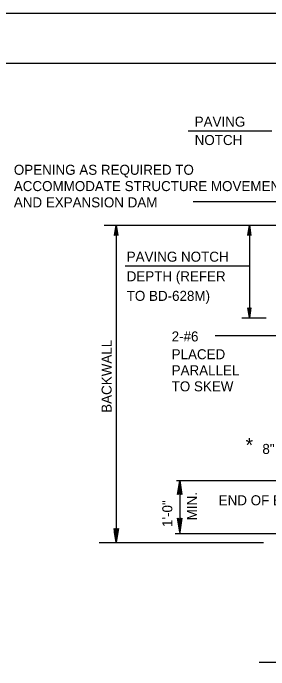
# Model space of a CAD drawing. Extents: x 638653 to 642302, y 298557 to 300414.
# Drawn here: x 640382.5 to 640459.2, y 300142.1 to 300338.5 of the extents above; entities that cross this region are included whole.
import ezdxf

# ---------------------------------------------------------------- set-up
doc = ezdxf.new("R2010")
doc.units = 0
doc.layers.add('1', color=7, linetype='Continuous')
doc.layers.add('PLT-BNDY', color=7, linetype='Continuous')

msp = doc.modelspace()

# ---------------------------------------------------------------- linework, layer by layer
at = {"layer": '1'}
for p, q in [((639863.16, 300323.52), (640649.16, 300323.52)), ((640459.99, 300303.19), (640434.96, 300303.19)), ((640436.48, 300282.18), (640481.83, 300282.18)), ((640409.78, 300275.05), (640472.49, 300275.05)), ((640413.42, 300275.05), (640413.42, 300180.15)), ((640453.3, 300275.05), (640453.3, 300247.34)), ((640416.12, 300262.89), (640453.3, 300262.89)), ((640451.07, 300247.34), (640458.32, 300247.34)), ((640443.08, 300242.12), (640499.13, 300242.12)), ((640431.48, 300198.74), (640503.46, 300198.74)), ((640432.43, 300198.69), (640432.43, 300182.8)), ((640432.43, 300198.38), (640432.43, 300183.22)), ((640431.1, 300182.8), (640496.8, 300182.8)), ((640408.27, 300180.15), (640457.51, 300180.15)), ((640456.22, 300144.37), (640490.46, 300144.37))]:
    msp.add_line(p, q, dxfattribs=at)
for points in [[(640413.06, 300272.14), (640413.27, 300272.25), (640413.42, 300275.05), (640413.06, 300272.14), (640412.93, 300271.99), (640413.42, 300275.05), (640413.56, 300272.25), (640413.77, 300272.15), (640413.42, 300275.05), (640413.91, 300271.99), (640413.77, 300272.15)], [(640452.93, 300272.14), (640453.14, 300272.25), (640453.3, 300275.05), (640452.93, 300272.14), (640452.81, 300271.99), (640453.3, 300275.05), (640453.44, 300272.25), (640453.65, 300272.15), (640453.3, 300275.05), (640453.78, 300271.99), (640453.65, 300272.15)], [(640453.66, 300250.24), (640453.45, 300250.13), (640453.3, 300247.34), (640453.66, 300250.24), (640453.79, 300250.39), (640453.3, 300247.34), (640453.16, 300250.13), (640452.95, 300250.23), (640453.3, 300247.34), (640452.81, 300250.39), (640452.95, 300250.23)], [(640431.96, 300194.63), (640432.27, 300194.79), (640432.43, 300198.69), (640431.96, 300194.63), (640431.81, 300194.47), (640432.43, 300198.69), (640432.59, 300194.79), (640432.9, 300194.63), (640432.43, 300198.69), (640433.06, 300194.47), (640432.9, 300194.63)], [(640431.96, 300194.63), (640432.27, 300194.79), (640432.43, 300198.69), (640431.96, 300194.63), (640431.81, 300194.47), (640432.43, 300198.69), (640432.59, 300194.79), (640432.9, 300194.63), (640432.43, 300198.69), (640433.06, 300194.47), (640432.9, 300194.63)], [(640432.9, 300187.29), (640432.59, 300187.13), (640432.43, 300183.22), (640432.9, 300187.29), (640433.06, 300187.44), (640432.43, 300183.22), (640432.27, 300187.13), (640431.96, 300187.29), (640432.43, 300183.22), (640431.81, 300187.44), (640431.96, 300187.29)], [(640413.89, 300184.21), (640413.58, 300184.05), (640413.42, 300180.15), (640413.89, 300184.21), (640414.05, 300184.37), (640413.42, 300180.15), (640413.27, 300184.05), (640412.96, 300184.21), (640413.42, 300180.15), (640412.8, 300184.37), (640412.96, 300184.21)], [(640413.79, 300183.05), (640413.58, 300182.95), (640413.42, 300180.15), (640413.79, 300183.05), (640413.92, 300183.2), (640413.42, 300180.15), (640413.29, 300182.94), (640413.08, 300183.05), (640413.42, 300180.15), (640412.94, 300183.2), (640413.08, 300183.05)]]:
    msp.add_lwpolyline(points, dxfattribs=at)
at = {"layer": 'PLT-BNDY'}
msp.add_lwpolyline([(639823.16, 300338.52), (640664.16, 300338.52), (640664.16, 299744.52), (639823.16, 299744.52)], close=True, dxfattribs=at)

# ---------------------------------------------------------------- texts
at = {"layer": '1'}
for s, height, p in [('PAVING', 3, (640436.92, 300304.55)), ('NOTCH', 3, (640436.92, 300299.06)), ('OPENING AS REQUIRED TO', 3, (640382.73, 300290.16)), ('ACCOMMODATE STRUCTURE MOVEMENT', 3, (640382.73, 300285.28)), ('AND EXPANSION DAM', 3, (640382.73, 300280.41)), ('PAVING NOTCH', 3, (640416.55, 300264.16)), ('DEPTH (REFER', 3, (640416.55, 300258.3)), ('TO BD-628M)', 3, (640416.55, 300252.44)), ('2-#6', 3, (640430.02, 300240.3)), ('PLACED', 3, (640430.02, 300234.97)), ('PARALLEL', 3, (640430.02, 300230.17)), ('TO SKEW', 3, (640430.02, 300225.37)), ('*', 4.32, (640452.18, 300207.14)), ('8" MIN.', 3, (640457.2, 300206.65)), ('END OF BEAM', 3, (640444.12, 300191.29))]:
    msp.add_text(s, height=height, dxfattribs=at).set_placement(p)
for s, p in [('BACKWALL', (640412.03, 300218.95)), ('MIN.', (640437.59, 300186.8)), ('1\'-0"', (640430.21, 300184.79))]:
    msp.add_text(s, height=3, rotation=90, dxfattribs=at).set_placement(p)

doc.saveas('drawing.dxf')
